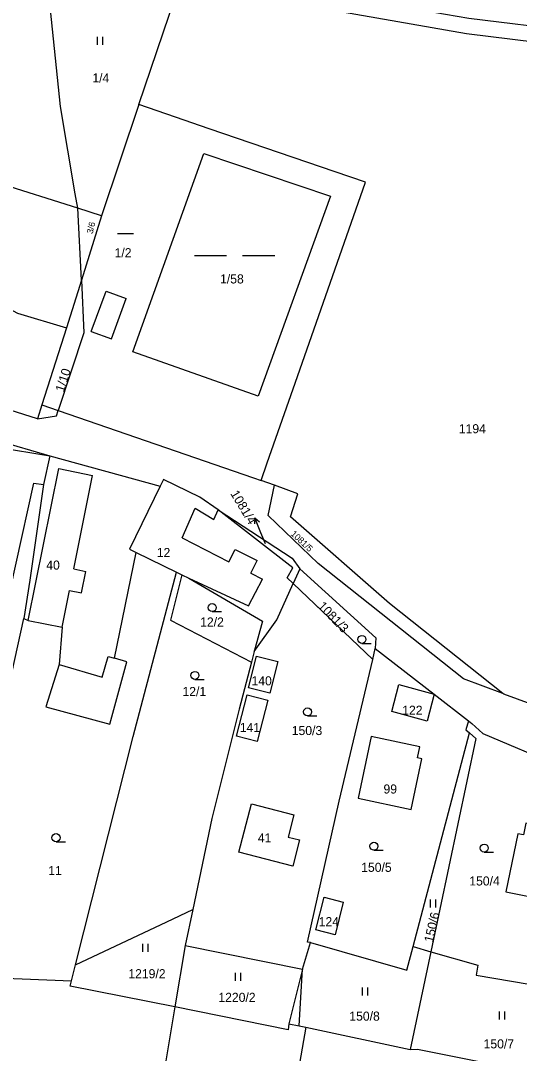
# Model space of a CAD drawing. Extents: x -746176 to -739709, y -1128407 to -1124482.
# Drawn here: x -742101.3 to -742008.2, y -1126433.2 to -1126240.2 of the extents above; entities that cross this region are included whole.
import ezdxf

# ---------------------------------------------------------------- set-up
doc = ezdxf.new("R2010")
doc.units = 0
for name, color, linetype in [('Vrstva 33', 7, 'Continuous'), ('Vrstva 42', 7, 'Continuous'), ('Vrstva 43', 7, 'Continuous'), ('Vrstva 44', 7, 'Continuous'), ('Vrstva 47', 7, 'Continuous')]:
    doc.layers.add(name, color=color, linetype=linetype)

msp = doc.modelspace()

# ---------------------------------------------------------------- linework, layer by layer
at = {"layer": 'Vrstva 33'}
for p, q in [((-742079.26, -1126255.9), (-742071.8, -1126233.98)), ((-742079.26, -1126255.9), (-742086.23, -1126276.66)), ((-742090.65, -1126275.25), (-742116.22, -1126267.19)), ((-742090.65, -1126275.25), (-742091.11, -1126272.55)), ((-742089.98, -1126288.73), (-742090.65, -1126275.25)), ((-742086.23, -1126276.66), (-742090.65, -1126275.25)), ((-742086.23, -1126276.66), (-742089.98, -1126288.73)), ((-742089.98, -1126288.73), (-742092.74, -1126297.6)), ((-742120.66, -1126314.22), (-742095.86, -1126321.55)), ((-742106.07, -1126319.87), (-742095.86, -1126321.55)), ((-742095.86, -1126321.55), (-742097.02, -1126326.92)), ((-742095.86, -1126321.55), (-742075.26, -1126327.22)), ((-742053.88, -1126327.04), (-742056.42, -1126326.16)), ((-742079.74, -1126339.61), (-742072.2, -1126343.28)), ((-742072.2, -1126343.28), (-742071.19, -1126343.77)), ((-742049.16, -1126342.68), (-742050.39, -1126345.41)), ((-742035.57, -1126359.6), (-742050.39, -1126345.41)), ((-742105.28, -1126372.36), (-742100.72, -1126351.93)), ((-742056.12, -1126352.45), (-742057.69, -1126358.14)), ((-742057.69, -1126358.14), (-742058.21, -1126360.09)), ((-742035.57, -1126359.6), (-742035.1, -1126357.57)), ((-742058.21, -1126360.09), (-742060.53, -1126368.87)), ((-742028.01, -1126413.28), (-742017.48, -1126373.34)), ((-742069.18, -1126406.33), (-742070.6, -1126413.05)), ((-742070.6, -1126413.05), (-742072.53, -1126424.54)), ((-742070.6, -1126413.05), (-742048.68, -1126417.48)), ((-742048.68, -1126417.48), (-742047.21, -1126412.52)), ((-742024.68, -1126414.24), (-742028.56, -1126432.53)), ((-742028.01, -1126413.28), (-742024.68, -1126414.24)), ((-742091.83, -1126419.68), (-742091.05, -1126416.72)), ((-742113.18, -1126418.78), (-742091.83, -1126419.68)), ((-742048.68, -1126417.48), (-742051.23, -1126427.71)), ((-742072.53, -1126424.54), (-742085.13, -1126499.75)), ((-742048.06, -1126428.34), (-742062.27, -1126510.43)), ((-742048.06, -1126428.34), (-742028.56, -1126432.53))]:
    msp.add_line(p, q, dxfattribs=at)
for points in [[(-742091.11, -1126272.55), (-742093.87, -1126256.26), (-742095.72, -1126238.15), (-742097.01, -1126230.58)], [(-741979.16, -1126247.44), (-742018.02, -1126242.67), (-742051.56, -1126236.78), (-742071.8, -1126233.98)], [(-742037.23, -1126236.37), (-742017.58, -1126239.71), (-741978.86, -1126244.46), (-741935.37, -1126247.86), (-741906.75, -1126240.11), (-741905.97, -1126243.01), (-741935.09, -1126250.9), (-741979.16, -1126247.44)], [(-742056.42, -1126326.16), (-742055.26, -1126322.85), (-742049.63, -1126306.73), (-742036.93, -1126270.38), (-742042.58, -1126268.45), (-742066.08, -1126260.42), (-742072.41, -1126258.25), (-742079.26, -1126255.9)], [(-742080.37, -1126302.09), (-742067.12, -1126265.01), (-742043.47, -1126273.03), (-742056.95, -1126310.39), (-742080.37, -1126302.09)], [(-742119.31, -1126276.84), (-742118.96, -1126285.81), (-742101.9, -1126294.87), (-742092.74, -1126297.6)], [(-742089.98, -1126288.73), (-742089.5, -1126298.57), (-742094.3, -1126313.08)], [(-742098.16, -1126314.66), (-742107.1, -1126311.81), (-742124.49, -1126306.28), (-742152.92, -1126294.67), (-742154.48, -1126293.27)], [(-742092.74, -1126297.6), (-742097.33, -1126312.04), (-742098.16, -1126314.66)], [(-742098.16, -1126314.66), (-742094.61, -1126314.04), (-742094.3, -1126313.08)], [(-742094.3, -1126313.08), (-742057.82, -1126325.67), (-742056.42, -1126326.16)], [(-742064.45, -1126331.63), (-742067.87, -1126329.27), (-742074.66, -1126325.97), (-742075.26, -1126327.22)], [(-742108.8, -1126371.54), (-742098.88, -1126326.64), (-742097.02, -1126326.92)], [(-742097.02, -1126326.92), (-742099.61, -1126344.81), (-742100.72, -1126351.93)], [(-742075.26, -1126327.22), (-742081, -1126339.01), (-742079.74, -1126339.61)], [(-742011.25, -1126365.95), (-742018.63, -1126363.2), (-742045.74, -1126341.65), (-742055.06, -1126332.67), (-742053.88, -1126327.04)], [(-742011.25, -1126365.95), (-742032.44, -1126349.16), (-742050.91, -1126332.94), (-742049.54, -1126328.65), (-742053.88, -1126327.04)], [(-742050.39, -1126345.41), (-742051.51, -1126344.33), (-742050.48, -1126342.5), (-742064.45, -1126331.63)], [(-742064.45, -1126331.63), (-742050.58, -1126340.65), (-742049.16, -1126342.68)], [(-742100.72, -1126351.93), (-742099.9, -1126352.31), (-742093.57, -1126353.58), (-742094.13, -1126360.58), (-742096.61, -1126368.48), (-742084.66, -1126371.69), (-742081.5, -1126360.05), (-742083.81, -1126359.38), (-742079.74, -1126339.61)], [(-742091.05, -1126416.72), (-742080.28, -1126374.02), (-742072.2, -1126343.28)], [(-742049.16, -1126342.68), (-742034.95, -1126355.55), (-742035.1, -1126357.57)], [(-742071.19, -1126343.77), (-742073.35, -1126352.28), (-742058.21, -1126360.09)], [(-742071.19, -1126343.77), (-742069.89, -1126344.4), (-742056.12, -1126352.45)], [(-742057.69, -1126358.14), (-742053.45, -1126352.23), (-742050.39, -1126345.41)], [(-742054.77, -1126365.88), (-742058.74, -1126364.92), (-742057.24, -1126358.99), (-742053.27, -1126359.99), (-742054.77, -1126365.88)], [(-742035.1, -1126357.57), (-742024.1, -1126366.11), (-742017.65, -1126371.11)], [(-742047.21, -1126412.52), (-742047.73, -1126412.44), (-742041.81, -1126386.09), (-742035.57, -1126359.6)], [(-742024.1, -1126366.11), (-742025.41, -1126371.14), (-742032, -1126369.36), (-742030.67, -1126364.32), (-742024.1, -1126366.11)], [(-742058.98, -1126366.22), (-742055.17, -1126367.22), (-742057.16, -1126374.93), (-742061.01, -1126373.94), (-742058.98, -1126366.22)], [(-741995.94, -1126371.66), (-741996.93, -1126371.29), (-742011.08, -1126366.08), (-742011.25, -1126365.95)], [(-742060.53, -1126368.87), (-742065.58, -1126389.34), (-742069.18, -1126406.33)], [(-742017.65, -1126371.11), (-742018.15, -1126372.75), (-742017.48, -1126373.34)], [(-742017.65, -1126371.11), (-742017.02, -1126371.6), (-742014.99, -1126373.44), (-741986.71, -1126385.43)], [(-742026.38, -1126378.16), (-742027.21, -1126377.99), (-742026.77, -1126375.94), (-742035.82, -1126374), (-742038.29, -1126385.53), (-742028.41, -1126387.64), (-742026.38, -1126378.16)], [(-742017.48, -1126373.34), (-742016.3, -1126374.36), (-742024.68, -1126414.24)], [(-742051.38, -1126392.8), (-742049.23, -1126393.33), (-742050.47, -1126398.22), (-742060.55, -1126395.61), (-742058.21, -1126386.6), (-742050.31, -1126388.63), (-742051.38, -1126392.8)], [(-742003.87, -1126389.15), (-742004.21, -1126390.8), (-742006.94, -1126390.24), (-742007.38, -1126392.41), (-742008.47, -1126392.19), (-742010.7, -1126403.03), (-742000.83, -1126405.05), (-741997.82, -1126390.4), (-742003.87, -1126389.15)], [(-742044.65, -1126404.04), (-742041.06, -1126404.95), (-742042.6, -1126411.06), (-742046.19, -1126410.15), (-742044.65, -1126404.04)], [(-742091.05, -1126416.72), (-742074.03, -1126408.64), (-742069.18, -1126406.33)], [(-742047.21, -1126412.52), (-742029.18, -1126417.71), (-742028.01, -1126413.28)], [(-742024.68, -1126414.24), (-742015.91, -1126416.77), (-742016.26, -1126418.65), (-742006.36, -1126420.29)], [(-742072.53, -1126424.54), (-742092.04, -1126420.67), (-742091.83, -1126419.68)], [(-742051.23, -1126427.71), (-742051.35, -1126428.82), (-742072.53, -1126424.54)], [(-742051.23, -1126427.71), (-742049.27, -1126428.1), (-742048.06, -1126428.34)], [(-742028.56, -1126432.53), (-742027.22, -1126432.46), (-742014.43, -1126435)]]:
    msp.add_lwpolyline(points, dxfattribs=at)
at = {"layer": 'Vrstva 43'}
for p, q in [((-742057.55, -1126333.16), (-742057.64, -1126334.27)), ((-742056.43, -1126335.94), (-742057.55, -1126333.16)), ((-742057.55, -1126333.16), (-742056.71, -1126333.9)), ((-742055.59, -1126337.98), (-742056.43, -1126335.94))]:
    msp.add_line(p, q, dxfattribs=at)
at = {"layer": 'Vrstva 44'}
for p, q in [((-742086.94, -1126244.72), (-742086.94, -1126243.22)), ((-742085.94, -1126244.72), (-742085.94, -1126243.22)), ((-742083.24, -1126280.01), (-742080.24, -1126280.01)), ((-742068.85, -1126284.1), (-742062.85, -1126284.1)), ((-742059.85, -1126284.1), (-742053.85, -1126284.1)), ((-742065.54, -1126350.67), (-742063.79, -1126350.67)), ((-742037.57, -1126356.61), (-742035.82, -1126356.61)), ((-742068.77, -1126363.34), (-742067.02, -1126363.34)), ((-742047.73, -1126370.16), (-742045.98, -1126370.16)), ((-742094.71, -1126393.67), (-742092.96, -1126393.67)), ((-742035.33, -1126395.27), (-742033.58, -1126395.27)), ((-742014.74, -1126395.61), (-742012.99, -1126395.61)), ((-742024.8, -1126405.99), (-742024.8, -1126404.49)), ((-742023.8, -1126405.99), (-742023.8, -1126404.49)), ((-742078.48, -1126414.25), (-742078.48, -1126412.75)), ((-742077.48, -1126414.25), (-742077.48, -1126412.75)), ((-742061.18, -1126419.71), (-742061.18, -1126418.21)), ((-742060.18, -1126419.71), (-742060.18, -1126418.21)), ((-742037.45, -1126422.4), (-742037.45, -1126420.9)), ((-742036.45, -1126422.4), (-742036.45, -1126420.9)), ((-742011.86, -1126426.93), (-742011.86, -1126425.43)), ((-742010.86, -1126426.93), (-742010.86, -1126425.43))]:
    msp.add_line(p, q, dxfattribs=at)
for centre in [(-742065.54, -1126349.92), (-742037.57, -1126355.86), (-742068.77, -1126362.59), (-742047.73, -1126369.41), (-742094.71, -1126392.92), (-742035.33, -1126394.52), (-742014.74, -1126394.86)]:
    msp.add_circle(centre, 0.75, dxfattribs=at)
at = {"layer": 'Vrstva 47'}
for p, q in [((-742088.12, -1126298.3), (-742085.35, -1126290.74)), ((-742085.35, -1126290.74), (-742081.58, -1126292.13)), ((-742084.35, -1126299.68), (-742081.58, -1126292.13)), ((-742088.12, -1126298.3), (-742084.35, -1126299.68)), ((-742097.33, -1126312.04), (-742094.3, -1126313.08)), ((-742099.9, -1126352.31), (-742094.21, -1126323.93)), ((-742094.21, -1126323.93), (-742087.88, -1126325.2)), ((-742091.39, -1126342.7), (-742087.88, -1126325.2)), ((-742071.15, -1126336.85), (-742068.73, -1126331.35)), ((-742068.73, -1126331.35), (-742065.22, -1126333.43)), ((-742065.22, -1126333.43), (-742064.45, -1126331.63)), ((-742071.15, -1126336.85), (-742062.44, -1126341.34)), ((-742062.44, -1126341.34), (-742061.28, -1126339.07)), ((-742061.28, -1126339.07), (-742057.13, -1126341.13)), ((-742058.33, -1126343.46), (-742057.13, -1126341.13)), ((-742091.39, -1126342.7), (-742089.14, -1126343.15)), ((-742089.94, -1126347.14), (-742089.14, -1126343.15)), ((-742058.33, -1126343.46), (-742056.16, -1126344.57)), ((-742069.89, -1126344.4), (-742058.75, -1126349.59)), ((-742058.75, -1126349.59), (-742056.16, -1126344.57)), ((-742093.57, -1126353.58), (-742092.19, -1126346.69)), ((-742092.19, -1126346.69), (-742089.94, -1126347.14)), ((-742086.12, -1126362.9), (-742085, -1126359.04)), ((-742085, -1126359.04), (-742083.81, -1126359.38)), ((-742094.13, -1126360.58), (-742086.12, -1126362.9)), ((-742049.27, -1126428.1), (-742048.68, -1126417.48))]:
    msp.add_line(p, q, dxfattribs=at)

# ---------------------------------------------------------------- texts
at = {"layer": 'Vrstva 42'}
for s, p in [('1/4', (-742087.92, -1126251.76)), ('1/2', (-742083.77, -1126284.43)), ('1/58', (-742064.07, -1126289.33)), ('1194', (-742019.48, -1126317.33)), ('12', (-742075.89, -1126340.47)), ('40', (-742096.53, -1126342.82)), ('12/2', (-742067.79, -1126353.46)), ('140', (-742058.2, -1126364.45)), ('12/1', (-742071.09, -1126366.45)), ('122', (-742030.05, -1126369.95)), ('141', (-742060.39, -1126373.18)), ('150/3', (-742050.68, -1126373.74)), ('99', (-742033.55, -1126384.67)), ('41', (-742057.02, -1126393.81)), ('150/5', (-742037.71, -1126399.31)), ('11', (-742096.16, -1126399.92)), ('150/4', (-742017.52, -1126401.86)), ('124', (-742045.65, -1126409.47)), ('1219/2', (-742081.2, -1126419.2)), ('1220/2', (-742064.39, -1126423.62)), ('150/8', (-742039.93, -1126427.13)), ('150/7', (-742014.85, -1126432.31))]:
    msp.add_text(s, height=1.7, dxfattribs=at).set_placement(p)
for s, height, rotation, p in [('3/6', 1.19, 76, (-742087.87, -1126280.14)), ('1/10', 1.7, 72, (-742093.27, -1126309.76)), ('1081/4', 1.7, 301, (-742062.21, -1126328.6)), ('1081/5', 1.19, 317, (-742050.97, -1126336.27)), ('1081/3', 1.7, 314, (-742045.93, -1126349.76)), ('150/6', 1.7, 77, (-742024.33, -1126412.62))]:
    msp.add_text(s, height=height, rotation=rotation, dxfattribs=at).set_placement(p)

doc.saveas('drawing.dxf')
